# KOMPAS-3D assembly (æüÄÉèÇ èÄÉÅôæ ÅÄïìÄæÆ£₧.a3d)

Referenced files in D:\АСКОН работа\Конкурс HOME\06_Сюваев_Сборная модель танка Т90\СБОРКИ\СБОРКА КОРПУСА ШТАМПОВКА\: СБОРКА КОРУС ХОДОВОЙ.a3d, Сборка полка надгусеничная левая.a3d, Сборка полка надгусеничная правая.a3d
Referenced files in D:\АСКОН работа\Конкурс HOME\06_Сюваев_Сборная модель танка Т90\ДЕТАЛИ\ОБЩИЕ ДЕТАЛИ\: бревно.m3d, откос левый.m3d, откос правый.m3d
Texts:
  СБОРКА КОРПУС ПОЛНОСТЬЮ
